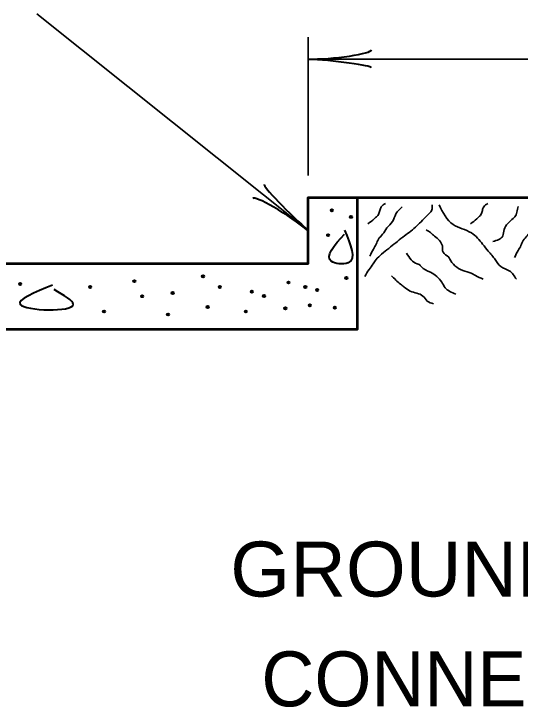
# Model space of a CAD drawing. Extents: x 12366 to 13046, y 9129 to 9570.
# Drawn here: x 12606.91 to 12629.98, y 9373.99 to 9405.55 of the extents above; entities that cross this region are included whole.
import ezdxf
from ezdxf.enums import TextEntityAlignment as Align

# ---------------------------------------------------------------- set-up
doc = ezdxf.new("R2010")
doc.units = 0
doc.layers.add('1', color=7, linetype='Continuous', lineweight=53)

msp = doc.modelspace()

# ---------------------------------------------------------------- linework, layer by layer
at = {"layer": '1', "lineweight": 35}
for p, q in [((12620.321, 9395.686), (12607.957, 9405.545)), ((12620.321, 9398.186), (12620.321, 9404.479)), ((12620.321, 9403.479), (12650.681, 9403.479))]:
    msp.add_line(p, q, dxfattribs=at)
at = {"layer": '1'}
for points in [[(12495.321, 9394.186), (12620.321, 9394.186), (12620.321, 9397.186), (12649.358, 9397.186)], [(12495.321, 9394.167), (12495.321, 9391.186), (12622.571, 9391.186), (12622.571, 9397.186)]]:
    msp.add_lwpolyline(points, dxfattribs=at)
at = {"layer": '1', "lineweight": 40}
for centre in [(12621.399, 9396.598), (12622.27, 9396.303), (12621.228, 9395.469), (12612.406, 9393.377), (12615.534, 9393.595), (12622.061, 9393.525), (12607.203, 9393.248), (12610.393, 9393.109), (12616.298, 9393.109), (12619.423, 9393.317), (12620.187, 9393.109), (12614.151, 9392.84), (12617.756, 9392.901), (12620.728, 9392.975), (12612.757, 9392.692), (12618.312, 9392.706), (12615.743, 9392.206), (12619.284, 9392.137), (12620.395, 9392.276), (12621.533, 9392.169), (12611.021, 9391.998), (12613.937, 9391.859), (12617.479, 9391.998)]:
    msp.add_circle(centre, 0.05, dxfattribs=at)
for centre, major_axis, ratio, start_param, end_param in [((12621.412, 9403.755), (-1.786, -0.156), 0.122415, 0.896353, 3.141593), ((12621.412, 9403.755), (-1.786, -0.156), 0.122415, 0.896353, 3.141593), ((12621.441, 9403.268), (-1.756, 0.176), 0.07063, 3.140715, 5.41811), ((12621.441, 9403.268), (-1.756, 0.176), 0.07063, 3.140715, 5.41811), ((12619.577, 9396.55), (1.264, -1.232), 0.07063, 3.140715, 5.41811), ((12619.296, 9396.151), (1.494, -0.991), 0.122415, 0.896353, 3.141593)]:
    msp.add_ellipse(centre, major_axis=major_axis, ratio=ratio, start_param=start_param, end_param=end_param, dxfattribs=at)
at = {"layer": '1', "lineweight": 35}
for points in [[(12623.841, 9396.919), (12623.649, 9396.759), (12623.585, 9396.599), (12623.521, 9396.407), (12623.393, 9396.279), (12623.329, 9396.215), (12623.041, 9395.991)], [(12628.511, 9396.919), (12628.319, 9396.759), (12628.255, 9396.599), (12628.191, 9396.407), (12628.063, 9396.279), (12627.999, 9396.215), (12627.711, 9395.991)], [(12625.971, 9396.853), (12625.971, 9396.725), (12625.907, 9396.533), (12625.78, 9396.405), (12625.652, 9396.277), (12625.396, 9396.021), (12625.204, 9395.829), (12624.628, 9395.381), (12624.308, 9395.125), (12623.668, 9394.613), (12623.412, 9394.357), (12623.284, 9394.165), (12623.092, 9393.91), (12622.901, 9393.59)], [(12624.607, 9396.759), (12624.319, 9396.439), (12624.159, 9396.087), (12623.903, 9395.799), (12623.711, 9395.511), (12623.519, 9395.287), (12623.423, 9395.063), (12623.295, 9394.84), (12623.135, 9394.52)], [(12626.283, 9396.852), (12626.923, 9395.957), (12627.754, 9395.573), (12628.266, 9395.061), (12628.522, 9394.741), (12628.842, 9394.357), (12629.098, 9394.038), (12629.482, 9393.846), (12629.802, 9393.462)], [(12628.734, 9395.181), (12629.182, 9395.437), (12629.246, 9395.725), (12629.662, 9396.236), (12629.789, 9396.396), (12629.853, 9396.652), (12629.885, 9396.78)], [(12631.197, 9396.695), (12630.909, 9396.375), (12630.749, 9396.023), (12630.493, 9395.735), (12630.301, 9395.447), (12630.109, 9395.223), (12630.013, 9394.999), (12629.885, 9394.775), (12629.725, 9394.456)], [(12625.696, 9395.715), (12625.888, 9395.587), (12626.08, 9395.427), (12626.432, 9394.98), (12626.464, 9394.692), (12626.72, 9394.468), (12626.816, 9394.308), (12627.456, 9393.828), (12627.84, 9393.7), (12627.936, 9393.636), (12628.288, 9393.476)], [(12624.802, 9394.649), (12625.282, 9394.169), (12625.378, 9394.137), (12625.474, 9394.041), (12625.89, 9393.785), (12626.402, 9393.337), (12626.561, 9393.081), (12627.041, 9392.793)], [(12624.11, 9393.626), (12624.525, 9393.242), (12624.685, 9393.114), (12624.973, 9392.922), (12625.549, 9392.698), (12625.741, 9392.474), (12626.029, 9392.346)]]:
    msp.add_spline(points, degree=3, dxfattribs=at)
at = {"layer": '1', "lineweight": 40}
for points in [[(12621.969, 9395.692), (12622.137, 9394.216), (12621.365, 9394.283), (12621.969, 9395.524)], [(12608.682, 9393.192), (12607.205, 9392.32), (12609.621, 9392.32), (12608.749, 9392.991)]]:
    msp.add_spline(points, degree=3, dxfattribs=at)

# ---------------------------------------------------------------- texts
at = {"layer": '1', "width": 1.05}
msp.add_text('GROUND ROD', height=2.5, dxfattribs=at).set_placement((12628.96, 9379.023), align=Align.CENTER)
at = {"layer": '1'}
msp.add_text('CONNECTOR', height=2.5, dxfattribs=at).set_placement((12628.96, 9374.023), align=Align.CENTER)

doc.saveas('drawing.dxf')
